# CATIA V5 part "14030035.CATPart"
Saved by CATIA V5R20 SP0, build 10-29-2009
Part number: 14030035
Definition: NONE
Nomenclature: 14030035
Source: Unknown
Description: 14030035
Bounding box of the stored display mesh (mm): x -17.5 to 70, y -29 to 18.906, z -19.1 to 19.1
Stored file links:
  C:\Users\Utente\Desktop\IO LAVORO\3D X SITO CF\X SITO\PLASTICA\RF2\14030035.CATPart
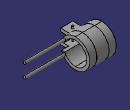
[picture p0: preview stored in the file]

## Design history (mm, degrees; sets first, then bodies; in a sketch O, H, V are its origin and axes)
Body1 "14030035" (main body)
  Solid1: solid without history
